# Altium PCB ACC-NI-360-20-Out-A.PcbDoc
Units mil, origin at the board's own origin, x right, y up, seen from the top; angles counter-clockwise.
Board outline 1500 x 3250 mil, 2 copper layers (Top Layer, Bottom Layer), stack 22.756 mil thick; 15 components, 12 nets, 49 pads, 438 vias.
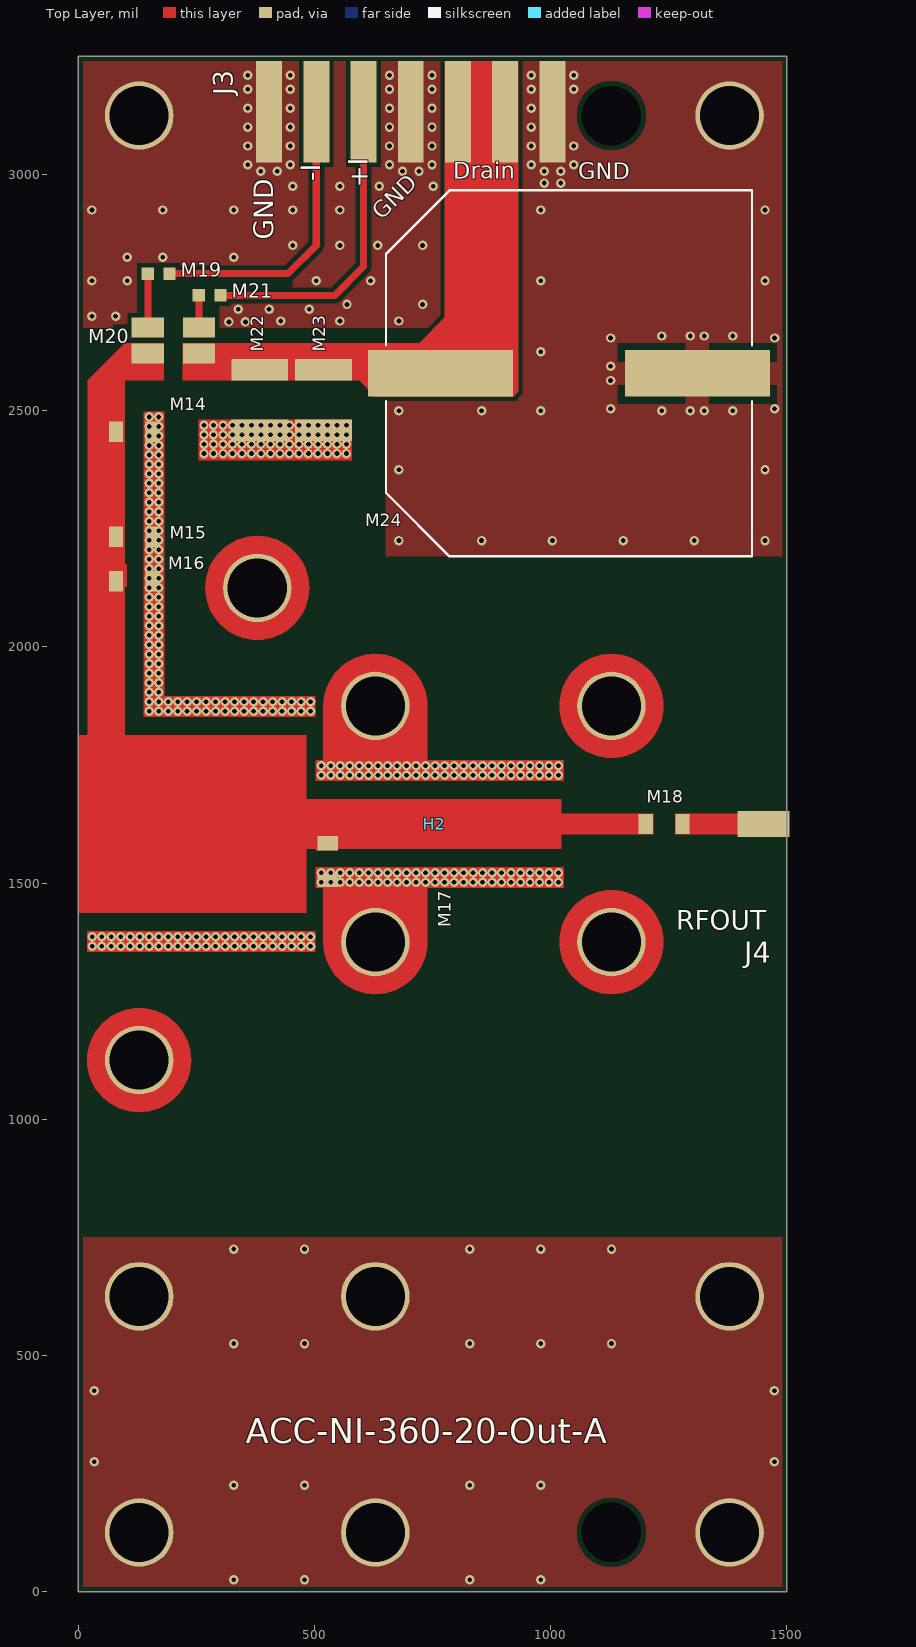
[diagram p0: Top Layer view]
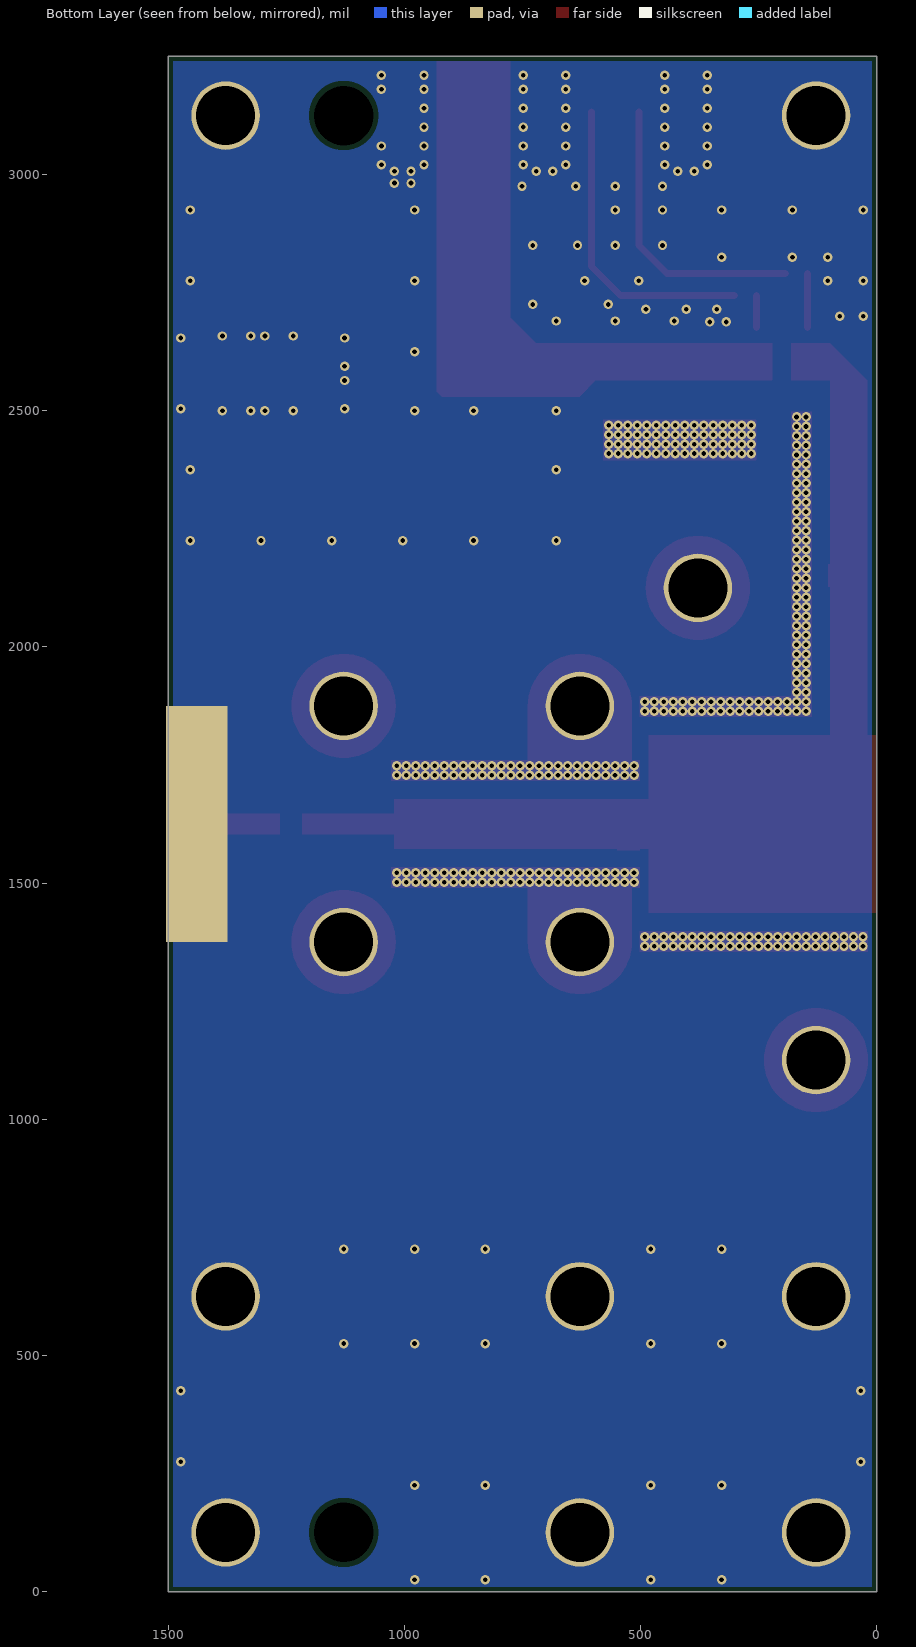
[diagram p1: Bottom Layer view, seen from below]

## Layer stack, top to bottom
Top Layer: signal copper 1.378
Dielectric 1: prepreg 20, RO4350B, Dk 3.48
Bottom Layer: signal copper 1.378

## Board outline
0,0 0,3250 1500,3250 1500,0

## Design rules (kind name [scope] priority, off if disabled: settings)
BackDrilling [IsVia and not InNet('GND')] p1: maxstublength=5 usetopbackdrill=TRUE usebottombackdrill=TRUE holeoversize=10 holetolplus=0.2 holetolminus=0.2
BoardOutlineClearance BoardOutlineClearance_Solder_Mask [OnLayer('Top Solder') Or OnLayer('Bottom Solder')] p1: gap=0 ignorepadtopadclearanceinfootprint=FALSE
BoardOutlineClearance [All] p2: gap=10 ignorepadtopadclearanceinfootprint=FALSE
Clearance Clearance_I/O [InNetClass('I/O') vs InNet('GND')] p1: gap=7 ignorepadtopadclearanceinfootprint=TRUE
Clearance Clearance_RF_Strip [InNetClass('RF_Strip') vs InNet('GND')] p2: gap=40 ignorepadtopadclearanceinfootprint=TRUE
Clearance Clearance_RF_15-15-8 [InNetClass('RF_15-15-8') vs InNet('GND')] p3: gap=15 ignorepadtopadclearanceinfootprint=TRUE
Clearance Clearance_RF_20-10-12 [InNetClass('RF_20-10-12') vs InNet('GND')] p4: gap=10 ignorepadtopadclearanceinfootprint=TRUE
Clearance Clearance_RF_30-20-16 [InNetClass('RF_30-20-16') vs InNet('GND')] p5: gap=20 ignorepadtopadclearanceinfootprint=TRUE
Clearance Clearance_RF_28-21-16_FR4 [InNetClass('RF_28-21-16_FR4') vs InNet('GND')] p6: gap=21 ignorepadtopadclearanceinfootprint=TRUE
Clearance Clearance_RF_15-27p5-8 [InNetClass('RF_15-27p5-8') vs InNet('GND')] p7: gap=27.5 ignorepadtopadclearanceinfootprint=TRUE
Clearance Clearance_RF_25-22-40_75ohm [InNetClass('RF_25-22-40_75ohm') vs InNet('GND')] p8: gap=22 ignorepadtopadclearanceinfootprint=TRUE
Clearance Clearance_GND [InNet('GND')] p9: gap=10 ignorepadtopadclearanceinfootprint=TRUE
Clearance [All] p10: gap=6 ignorepadtopadclearanceinfootprint=TRUE
ComponentClearance ComponentClearance_Heatsink [InComponent('All') And OnLayer('Top Layer') vs HasFootprint('Heatsink_wFid')] p1: gap=0 collisioncheckmode=3 verticalgap=0 showdistances=FALSE
ComponentClearance ComponentClearance_PCB_Frame [InComponent('All') And OnLayer('Top Layer') vs HasFootprint('PCB_Frame')] p2: gap=0 collisioncheckmode=3 verticalgap=0 showdistances=FALSE
ComponentClearance [All] p3: gap=10 collisioncheckmode=3 verticalgap=10 showdistances=TRUE
HoleSize [All] p1: absolutevalues=TRUE maxlimit=200 minlimit=8 maxpercent=80.000 minpercent=20.000
MinimumSolderMaskSliver [All] p1: minsoldermaskwidth=5
PlaneClearance [Not InNet('GND')] p1: clearance=20
PlaneConnect [InNet('GND')] p1: planeconnectstyle=Direct reliefexpansion=20 reliefentries=4 reliefconductorwidth=10 reliefairgap=10
PolygonConnect [All vs InNet('GND')] p1: connectstyle=Direct reliefconductorwidth=10 reliefentries=4 polygonreliefangle="90 Angle" airgapwidth=10
RoutingVias [All] p1: holewidth=10 width=20 viastyle="Through Hole" minholewidth=8 minwidth=18 maxholewidth=23.62 maxwidth=33.62
SilkToSilkClearance [All] p1: silktosilkclearance=5
SilkToSolderMaskClearance [IsPad] p1: minsilkscreentomaskgap=5 clearancetoexposedcopper=TRUE
SolderMaskExpansion [All] p1: expansion=1 istentingtop=FALSE
UnRoutedNet [All] p1: checkbadconnections=TRUE
Width [All] p1: maxlimit=100 minlimit=6 preferedwidth=10
22 further rules are at their usual default settings.

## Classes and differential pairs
component class ACC-NI-360-xx-20-A: H2 J4 M14 M15 M16 M17 M18 M19 M20 M21 M22 M23 M24
net class RF_Strip: NetJ1_1 NetJ3_1 NetM1_1 NetM4_1 NetM14_2

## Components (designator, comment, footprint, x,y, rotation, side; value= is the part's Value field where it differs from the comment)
F66 "Comment" PCB_Fab_30T-20G-16D_4003 -466.18,126.8 r0 top locked
H2 "Cooling_Block_Grid" Cooling_Block_Grid 128.5,1625 r0 top locked (schematic designator H1)
J3 "Header_H_7-Pin_100mil" Header_H_7-Pin_100mil 703.5,3250 r0 top (schematic designator J2B)
J4 "SMA Panel Mount_RevB" "SMA Panel Mount_RevB" 1500,1625 r180 top (schematic designator J3)
M14 "0805_30x70x42" 0805_30x70x42 118.11,2455.71 r180 top (schematic designator C315)
M15 "0805_30x70x42" 0805_30x70x42 118.11,2233.27 r180 top (schematic designator C321)
M16 "0805_30x70x42" 0805_30x70x42 118.11,2138.78 r180 top (schematic designator C314)
M17 "0805_30x70x42" 0805_30x70x42 527.56,1545.2 r90 top (schematic designator C323)
M18 "0805_30x70x42" 0805_30x70x42 1240.16,1625 r180 top (schematic designator C101)
M19 "0402_26x26x20" 0402_26x26x20 169.79,2790.22 r0 top (schematic designator M9)
M20 "Ohmite_LVK12" Ohmite_LVK12 200.79,2648.62 r180 top (schematic designator M10)
M21 "0402_26x26x20" 0402_26x26x20 277.79,2744.22 r0 top (schematic designator M8)
M22 "1210_45x120x75" 1210_45x120x75 383.86,2522.61 r90 top (schematic designator C145)
M23 "1210_45x120x75" 1210_45x120x75 518.78,2522.61 r90 top (schematic designator C319)
M24 "Panasonic_K-Size" Panasonic_K-Size 1038.5,2579 r0 top (schematic designator M17)

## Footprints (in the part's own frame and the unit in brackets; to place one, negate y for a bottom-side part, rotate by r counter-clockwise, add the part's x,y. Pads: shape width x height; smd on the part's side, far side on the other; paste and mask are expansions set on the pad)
0402_26x26x20 [mil] "0402 RL (RF Choke)"
  rect 26x26 smd: 1(-23,0) 2(23,0)
0805_30x70x42 [mil] "Generic 0805 SMD"
  rect 30x43 smd: 1(-39,0) 2(39,0)
1210_45x120x75 [mil] "Generic 1210 SMD"
  rect 45x120 smd: 1(-64,0) 2(64,0)
Cooling_Block_Grid [mil] "Heatsink Mounting Holes"
  round 145 hole 125 paste-100 mask+37.5: 1(0,-1500) 1(0,-1000) 1(0,-500) 1(0,1500) 1(250,500) 1(500,-1500) 1(500,-1000) 1(500,-250) 1(500,250) 1(1000,-250) 1(1000,250) 1(1250,-1500) 1(1250,-1000) 1(1250,1500)
  round 0 hole 125.98 unplated paste-100 mask+20: 2(1000,-1500) 2(1000,1500)
Header_H_7-Pin_100mil [mil] "Generic Flat Header"
  rect 55x215 smd paste-28: 1(-300,-117.5) 2(-200,-117.5) 3(-100,-117.5) 4(0,-117.5) 5(100,-117.5) 6(200,-117.5) 7(300,-117.5)
Ohmite_LVK12 [mil] "Current Sense Resistor"
  rect 68x43 smd: 1(-54,-27.5) 2(54,-27.5) 3(54,27.5) 4(-54,27.5)
Panasonic_K-Size [mil] "EEV-FK2A221M Capacitor"
  rect 307x98.5 smd: 1(271.65,0) 2(-271.65,0)
  silkscreen extent -387,-387 387,387
PCB_Fab_30T-20G-16D_4003 [mil] "STD RF&Stack  30mil RF 20mil Gap  16mil Dielectric"
"SMA Panel Mount_RevB" [mil] "901-2GB100000AE"
  rect 110x55 smd paste-50: 1(50,0)
  rect 130x500 smd far side paste-50: 2(60,0)

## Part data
H2: library part "Mounting Holes"
J3: library part Header_7-Pin, "Header 7-Pin"
J4: library part RF_Conn
M14 M15 M16 M17 M18 M22 M23 M24: library part Capacitor
M19 M21: library part Resistor
M20: library part Resistor_Ohmite_Current_Sense

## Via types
v1: diameter 20/20 (per signal layer), hole 10, Top Layer to Bottom Layer, tented top, 312 vias
v2: diameter 20/20 (per signal layer), hole 10, Top Layer to Bottom Layer, 126 vias

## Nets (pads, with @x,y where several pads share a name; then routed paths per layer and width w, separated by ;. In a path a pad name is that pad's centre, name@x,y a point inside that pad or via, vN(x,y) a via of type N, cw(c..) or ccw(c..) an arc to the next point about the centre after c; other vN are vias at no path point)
GND: H2.1 J3.1 J3.4 J3.7 J4.2 M14.1 M15.1 M16.1 M17.1 M22.1 M23.1 M24.1
  other v1: 29.01,1366.12 49.11,1366.12 69.21,1366.12 89.31,1366.12 109.41,1366.12 129.51,1366.12 149.61,1366.12 169.71,1366.12 189.81,1366.12 209.91,1366.12 230.01,1366.12 250.11,1366.12 270.21,1366.12 290.31,1366.12 310.41,1366.12 330.51,1366.12 350.61,1366.12 370.71,1366.12 390.81,1366.12 410.91,1366.12 431,1366.12 451.1,1366.12 471.2,1366.12 491.3,1366.12 29.01,1386.22 49.11,1386.22 69.21,1386.22 89.31,1386.22 109.41,1386.22 129.51,1386.22 149.61,1386.22 169.71,1386.22 189.81,1386.22 209.91,1386.22 230.01,1386.22 250.11,1386.22 270.21,1386.22 290.31,1386.22 310.41,1386.22 330.51,1386.22 350.61,1386.22 370.71,1386.22 390.81,1386.22 410.91,1386.22 431,1386.22 451.1,1386.22 471.2,1386.22 491.3,1386.22 513.78,1501.55 533.88,1501.55 553.98,1501.55 574.08,1501.55 594.18,1501.55 614.28,1501.55 634.38,1501.55 654.48,1501.55 674.58,1501.55 694.68,1501.55 714.78,1501.55 734.88,1501.55 754.98,1501.55 775.08,1501.55 795.18,1501.55 815.28,1501.55 835.38,1501.55 855.48,1501.55 875.58,1501.55 895.68,1501.55 915.78,1501.55 935.88,1501.55 955.98,1501.55 976.08,1501.55 996.18,1501.55 1016.28,1501.55 513.78,1521.65 533.88,1521.65 553.98,1521.65 574.08,1521.65 594.18,1521.65 614.28,1521.65 634.38,1521.65 654.48,1521.65 674.58,1521.65 694.68,1521.65 714.78,1521.65 734.88,1521.65 754.98,1521.65 775.08,1521.65 795.18,1521.65 815.28,1521.65 835.38,1521.65 855.48,1521.65 875.58,1521.65 895.68,1521.65 915.78,1521.65 935.88,1521.65 955.98,1521.65 976.08,1521.65 996.18,1521.65 1016.28,1521.65 513.78,1728.35 533.88,1728.35 553.98,1728.35 574.08,1728.35 594.18,1728.35 614.28,1728.35 634.38,1728.35 654.48,1728.35 674.58,1728.35 694.68,1728.35 714.78,1728.35 734.88,1728.35 754.98,1728.35 775.08,1728.35 795.18,1728.35 815.28,1728.35 835.38,1728.35 855.48,1728.35 875.58,1728.35 895.68,1728.35 915.78,1728.35 935.88,1728.35 955.98,1728.35 976.08,1728.35 996.18,1728.35 1016.28,1728.35 513.78,1748.45 533.88,1748.45 553.98,1748.45 574.08,1748.45 594.18,1748.45 614.28,1748.45 634.38,1748.45 654.48,1748.45 674.58,1748.45 694.68,1748.45 714.78,1748.45 734.88,1748.45 754.98,1748.45 775.08,1748.45 795.18,1748.45 815.28,1748.45 835.38,1748.45 855.48,1748.45 875.58,1748.45 895.68,1748.45 915.78,1748.45 935.88,1748.45 955.98,1748.45 976.08,1748.45 996.18,1748.45 1016.28,1748.45 149.61,1863.78 169.71,1863.78 189.81,1863.78 209.91,1863.78 230.01,1863.78 250.11,1863.78 270.21,1863.78 290.31,1863.78 310.41,1863.78 330.51,1863.78 350.61,1863.78 370.71,1863.78 390.81,1863.78 410.91,1863.78 431,1863.78 451.1,1863.78 471.2,1863.78 491.3,1863.78 149.61,1883.88 169.71,1883.88 189.81,1883.88 209.91,1883.88 230.01,1883.88 250.11,1883.88 270.21,1883.88 290.31,1883.88 310.41,1883.88 330.51,1883.88 350.61,1883.88 370.71,1883.88 390.81,1883.88 410.91,1883.88 431,1883.88 451.1,1883.88 471.2,1883.88 491.3,1883.88 149.61,1903.98 169.71,1903.98 149.61,1924.08 169.71,1924.08 149.61,1944.18 169.71,1944.18 149.61,1964.28 169.71,1964.28 149.61,1984.38 169.71,1984.38 149.61,2004.48 169.71,2004.48 149.61,2024.58 169.71,2024.58 149.61,2044.68 169.71,2044.68 149.61,2064.78 169.71,2064.78 149.61,2084.88 169.71,2084.88 149.61,2104.98 169.71,2104.98 149.61,2125.08 169.71,2125.08 149.61,2145.18 169.71,2145.18 149.61,2165.28 169.71,2165.28 149.61,2185.38 169.71,2185.38 149.61,2205.48 169.71,2205.48 149.61,2225.58 169.71,2225.58 149.61,2245.68 169.71,2245.68 149.61,2265.78 169.71,2265.78 149.61,2285.88 169.71,2285.88 149.61,2305.98 169.71,2305.98 149.61,2326.08 169.71,2326.08 149.61,2346.18 169.71,2346.18 149.61,2366.28 169.71,2366.28 149.61,2386.38 169.71,2386.38 149.61,2406.48 169.71,2406.48 265.75,2409.19 285.85,2409.19 305.95,2409.19 326.05,2409.19 346.15,2409.19 366.25,2409.19 386.35,2409.19 406.44,2409.19 426.54,2409.19 446.64,2409.19 466.74,2409.19 486.84,2409.19 506.94,2409.19 527.04,2409.19 547.14,2409.19 567.24,2409.19 149.61,2426.58 169.71,2426.58 265.75,2429.29 285.85,2429.29 305.95,2429.29 326.05,2429.29 346.15,2429.29 366.25,2429.29 386.35,2429.29 406.44,2429.29 426.54,2429.29 446.64,2429.29 466.74,2429.29 486.84,2429.29 506.94,2429.29 527.04,2429.29 547.14,2429.29 567.24,2429.29 149.61,2446.68 169.71,2446.68 265.75,2449.39 285.85,2449.39 305.95,2449.39 326.05,2449.39 346.15,2449.39 366.25,2449.39 386.35,2449.39 406.44,2449.39 426.54,2449.39 446.64,2449.39 466.74,2449.39 486.84,2449.39 506.94,2449.39 527.04,2449.39 547.14,2449.39 567.24,2449.39 149.61,2466.78 169.71,2466.78 265.75,2469.49 285.85,2469.49 305.95,2469.49 326.05,2469.49 346.15,2469.49 366.25,2469.49 386.35,2469.49 406.44,2469.49 426.54,2469.49 446.64,2469.49 466.74,2469.49 486.84,2469.49 506.94,2469.49 527.04,2469.49 547.14,2469.49 567.24,2469.49 149.61,2486.88 169.71,2486.88
  other v2: 328.5,25 478.5,25 828.5,25 978.5,25 328.5,225 478.5,225 828.5,225 978.5,225 33.5,275 1473.5,275 33.5,425 1473.5,425 328.5,525 478.5,525 828.5,525 978.5,525 1128.5,525 328.5,725 478.5,725 828.5,725 978.5,725 1128.5,725 678.5,2225 853.5,2225 1003.5,2225 1153.5,2225 1303.5,2225 1453.5,2225 678.5,2375 1453.5,2375 678.5,2500 853.5,2500 978.5,2500 1235.15,2499.79 1295.15,2499.79 1325.15,2499.79 1385.15,2499.79 1126.61,2504 1473.7,2504 1126.61,2564 1126.61,2594 978.5,2625 1126.61,2654 1473.7,2654 1235.15,2658.21 1295.15,2658.21 1325.15,2658.21 1385.15,2658.21 318.5,2688 353.5,2688 428.5,2690 553.5,2690 678.5,2690 28.5,2700 78.5,2700 338.5,2715 403.5,2715 488.5,2715 568.5,2725 728.5,2725 28.5,2775 103.5,2775 503.5,2775 618.5,2775 978.5,2775 1453.5,2775 103.5,2825 178.5,2825 328.5,2825 453.5,2850 553.5,2850 633.5,2850 728.5,2850 28.5,2925 178.5,2925 328.5,2925 453.5,2925 553.5,2925 978.5,2925 1453.5,2925 453.5,2975 553.5,2975 637,2975 751,2975 986,2982 1021,2982 386,3007 421,3007 686,3007 721,3007 986,3007 1021,3007 358.5,3020.5 448.5,3020.5 658.5,3020.5 748.5,3020.5 958.5,3020.5 1048.5,3020.5 358.5,3060.5 448.5,3060.5 658.5,3060.5 748.5,3060.5 958.5,3060.5 1048.5,3060.5 358.5,3100.5 448.5,3100.5 658.5,3100.5 748.5,3100.5 958.5,3100.5 358.5,3140.5 448.5,3140.5 658.5,3140.5 748.5,3140.5 958.5,3140.5 358.5,3180.5 448.5,3180.5 658.5,3180.5 748.5,3180.5 958.5,3180.5 1048.5,3180.5 358.5,3210.5 448.5,3210.5 658.5,3210.5 748.5,3210.5 958.5,3210.5 1048.5,3210.5
NetJ1_1: 
NetJ2A_2: 
NetJ2B_2: J3.2 M19.2 | length 618
  Top Layer w15: M19.2 443.72,2790.22 503.5,2850 J3.2
NetJ2B_3: J3.3 M21.2 | length 655.4
  Top Layer w15: M21.2 542.72,2744.22 603.5,2805 J3.3
NetJ2B_5: J3.5 J3.6 M20.4 M22.2 M23.2 M24.2
NetJ3_1: J4.1 M18.1
NetM1_1: 
NetM4_1: 
NetM14_2: M14.2 M15.2 M16.2 M17.2 M18.2 M20.3
NetM19_1: M19.1 M20.2 | length 114.1
  Top Layer w15: M20.2 M19.1
NetM20_1: M20.1 M21.1 | length 68.1
  Top Layer w15: M20.1 M21.1
pads on no net: H2.2

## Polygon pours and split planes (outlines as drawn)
GND on Top Layer "NONET_L-01_P-001" (solid, pour order 1): 0,0 0,750 1500,750 1500,0
GND on Top Layer "NONET_L-01_P-001" (solid, pour order 5): 0,3250 0,2676.12 651.05,2676.12 651.05,2191.55 1500,2191.55 1500,3250
no net on Bottom Solder "NONET_L-01_P-001" (solid): 0,3250 0,0 1500,0 1500,3250 1106.82,3250
no net on Top Solder "NONET_L-01_P-001" (solid): 0,3250 0,0 1500,0 1500,3250
GND on Bottom Layer "NONET_L-01_P-001" (solid, pour order 3): 0,3250 1500,3250 1500,0 0,0

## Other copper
Top Layer:
  region net GND: 488.5,2125 ccw(c378.5,2125) 378.5,2235 ccw(c378.5,2125) 268.5,2125 ccw(c378.5,2125) 378.5,2015 ccw(c378.5,2125)
  region net GND: 1128.5,1765 ccw(c1128.5,1875) 1238.5,1875 ccw(c1128.5,1875) 1128.5,1985 ccw(c1128.5,1875) 1018.5,1875 ccw(c1128.5,1875)
  region net GND: 518.5,1875 ccw(c628.5,1875) 628.5,1765 ccw(c628.5,1875) 738.5,1875 ccw(c628.5,1875) 628.5,1985 ccw(c628.5,1875)
  region net GND: 738.5,1375 ccw(c628.5,1375) 628.5,1485 ccw(c628.5,1375) 518.5,1375 ccw(c628.5,1375) 628.5,1265 ccw(c628.5,1375)
  region net GND: 1128.5,1265 ccw(c1128.5,1375) 1238.5,1375 ccw(c1128.5,1375) 1128.5,1485 ccw(c1128.5,1375) 1018.5,1375 ccw(c1128.5,1375)
  region net GND: 128.5,1235 ccw(c128.5,1125) 18.5,1125 ccw(c128.5,1125) 128.5,1015 ccw(c128.5,1125) 238.5,1125 ccw(c128.5,1125)
  region net NetM14_2: 0,1812.6 482.28,1812.6 482.28,1677.17 1021.65,1677.17 1021.65,1646.5 1216.54,1646.5 1216.54,1603.5 1021.65,1603.5 1021.65,1572.83 549.21,1572.83 549.21,1568.9 501.97,1568.9 501.97,1572.83 482.28,1572.83 482.28,1437.4 0,1437.4
  pour cut-out: 123.79,2775 453.5,2775 453.5,2731.22 298.79,2731.22 298.79,2697.62 123.79,2697.62
  pour cut-out: 651.05,2676.12 743.5,2676.12 743.5,2675 721.22,2652.72 651.05,2652.72
  region net GND: 518.5,1875 518.5,1748.45 738.5,1748.45 738.5,1875
  region net GND: 738.5,1375 738.5,1501.55 518.5,1501.55 518.5,1375
  region net NetJ2B_5: 776,3240 931,3240 931,2540.4 920.35,2529.75 628.75,2529.75 594.52,2563.98 588.5,2563.98 588.5,2642.72 721.22,2642.72 776,2697.5
  region net NetJ2B_5: 220.79,2563.98 598.43,2563.98 598.43,2642.72 220.79,2642.72
  region net NetM14_2: 19.68,2563.98 98.43,2642.72 180.79,2642.72 180.79,2563.98 98.43,2563.98 98.43,2174.8 102.36,2174.8 102.36,2127.56 98.51,2127.56 98.43,2127.65 98.43,1625 19.68,1625
  region net GND: 254.5,2481.3 254.5,2394.69 579.06,2394.69 579.06,2481.3
  region net GND: 18.5,1354.72 18.5,1398.03 501.5,1398.03 501.5,1354.72
  region net GND: 181.1,1851.97 137.8,1851.97 137.8,2498 181.1,2498
  region net GND: 181.1,1895.28 181.1,1851.97 501.5,1851.97 501.5,1895.28
  region net GND: 501.97,1533.46 501.97,1490.16 1027.5,1490.16 1027.5,1533.46
  region net GND: 501.97,1716.54 501.97,1759.84 1027.5,1759.84 1027.5,1716.54
  region net NetJ3_1: 1263.78,1646.5 1500,1646.5 1500,1603.5 1263.78,1603.5

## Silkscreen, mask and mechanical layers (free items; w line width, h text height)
Top Overlay:
  text "-I" at 525.92,2986.28 h70 r90
  text "Drain" at 793.31,2979.1 h60
  text "GND" at 1058.5,2978.8 h60
  text "+I" at 625.92,2972.03 h70 r90
  text "GND" at 650.28,2894.13 h60 r45
  text "GND" at 425.92,2862.42 h70 r90
  text "RFOUT" at 1265.44,1387.58 h70
  text "ACC-NI-360-20-Out-A" at 353.74,296.18 h90
Top Solder:
  rectangle: 1181.1,1599.41 1224.41,1650.59
  region: 1299.21,1650.59 1255.91,1650.59 1255.91,1599.41 1299.21,1599.41
  region: 501.97,1604.25 501.97,1560.95 553.15,1560.95 553.15,1604.25
  region: 553.15,1486.14 553.15,1529.45 501.97,1529.45 501.97,1486.14
  region: 177.17,2164.37 133.86,2164.37 133.86,2113.19 177.17,2113.19
  rectangle: 59.06,2113.19 102.36,2164.37
  region: 177.17,2258.86 133.86,2258.86 133.86,2207.68 177.17,2207.68
  rectangle: 59.06,2207.68 102.36,2258.86
  region: 177.17,2481.3 133.86,2481.3 133.86,2430.12 177.17,2430.12
  rectangle: 59.06,2430.12 102.36,2481.3
  pour cut-out: 1283.5,1655 1283.5,1695 1198.5,1695 1198.5,1655
  pour cut-out: 1253.5,1445 1500,1445 1500,1305 1253.5,1305
  pour cut-out: 268.5,2148.78 268.5,2188.78 183.5,2188.78 183.5,2148.78
  pour cut-out: 273.5,2213.27 273.5,2253.27 188.5,2253.27 188.5,2213.27
  pour cut-out: 273.5,2485.71 273.5,2525.71 188.5,2525.71 188.5,2485.71
  pour cut-out: 763.5,1400 803.5,1400 803.5,1485 763.5,1485
  pour cut-out: 0,0 0,775 1500,775 1500,0
  pour cut-out: 0,3250 0,2583.85 313.5,2583.85 313.5,2619.11 588.5,2619.11 588.5,2175 1500,2175 1500,3250
  pour cut-out: 448.78,2619.11 588.78,2619.11 588.78,2423 448.78,2423 448.78,2436.11
  pour cut-out: 313,2619.11 453.86,2619.11 453.86,2423 313,2423
  pour cut-out: 1173.23,1658.46 1173.23,1591.54 1307.09,1591.54 1307.09,1658.46
Board_Dimension:
  the board outline again, w10
Drill Drawing:
  lines w15: -1463.06,-2604.01 3621.55,-2604.01 ; -1463.06,-2154.01 3621.55,-2154.01 ; -912.18,-2754.01 -912.18,-2004.01 ; -312.34,-2754.01 -312.34,-2004.01 ; 837.32,-2754.01 837.32,-2004.01 ; 1343.2,-2754.01 1343.2,-2004.01 ; 2077,-2754.01 2077,-2004.01 ; -1463.06,-2754.01 3621.55,-2754.01 3621.55,-2004.01 -1463.06,-2004.01 -1463.06,-2754.01
  text "Symbol" at -1373.06,-2109.01 h72
  text "Count" at -867.18,-2109.01 h72
  text "Hole Size" at -267.34,-2109.01 h72
  text "Plated" at 882.32,-2109.01 h72
  text "Hole Type" at 1388.2,-2109.01 h72
  text "Drill Layer Pair" at 2122,-2109.01 h72
  text "438" at -867.18,-2259.01 h60
  text "10.00mil (0.254mm)" at -267.34,-2259.01 h60
  text "PTH" at 882.32,-2259.01 h60
  text "Round" at 1388.2,-2259.01 h60
  text "Top Layer - Bottom Layer" at 2122,-2259.01 h60
  text "B" at -1402.15,-2269 h66.67
  text "14" at -867.18,-2409.01 h60
  text "125.00mil (3.175mm)" at -267.34,-2409.01 h60
  text "PTH" at 882.32,-2409.01 h60
  text "Round" at 1388.2,-2409.01 h60
  text "Top Layer - Bottom Layer" at 2122,-2409.01 h60
  text "H" at -1402.15,-2419 h66.67
  text "2" at -867.18,-2559.01 h60
  text "125.98mil (3.200mm)" at -267.34,-2559.01 h60
  text "NPTH" at 882.32,-2559.01 h60
  text "Round" at 1388.2,-2559.01 h60
  text "Top Layer - Bottom Layer" at 2122,-2559.01 h60
  text "N" at -1402.15,-2569 h66.67
  text "454 Total" at -867.18,-2709.01 h60
Document:
  lines w10: 1054.35,2929.33 1188.96,3346.93 ; 1090,1626 1759,2384 1325,1624 ; 1525,1373.36 1550,1373.36 1550,1873.36 1525,1873.36 ; 1550,1623.36 1900,1923.36 ; 785.96,2729.33 1385.96,2729.33 1385.96,2929.33 785.96,2929.33 785.96,2729.33

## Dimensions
0,0 to 0,3250 on Mechanical 16
0,0 to 1500,0 on Mechanical 16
